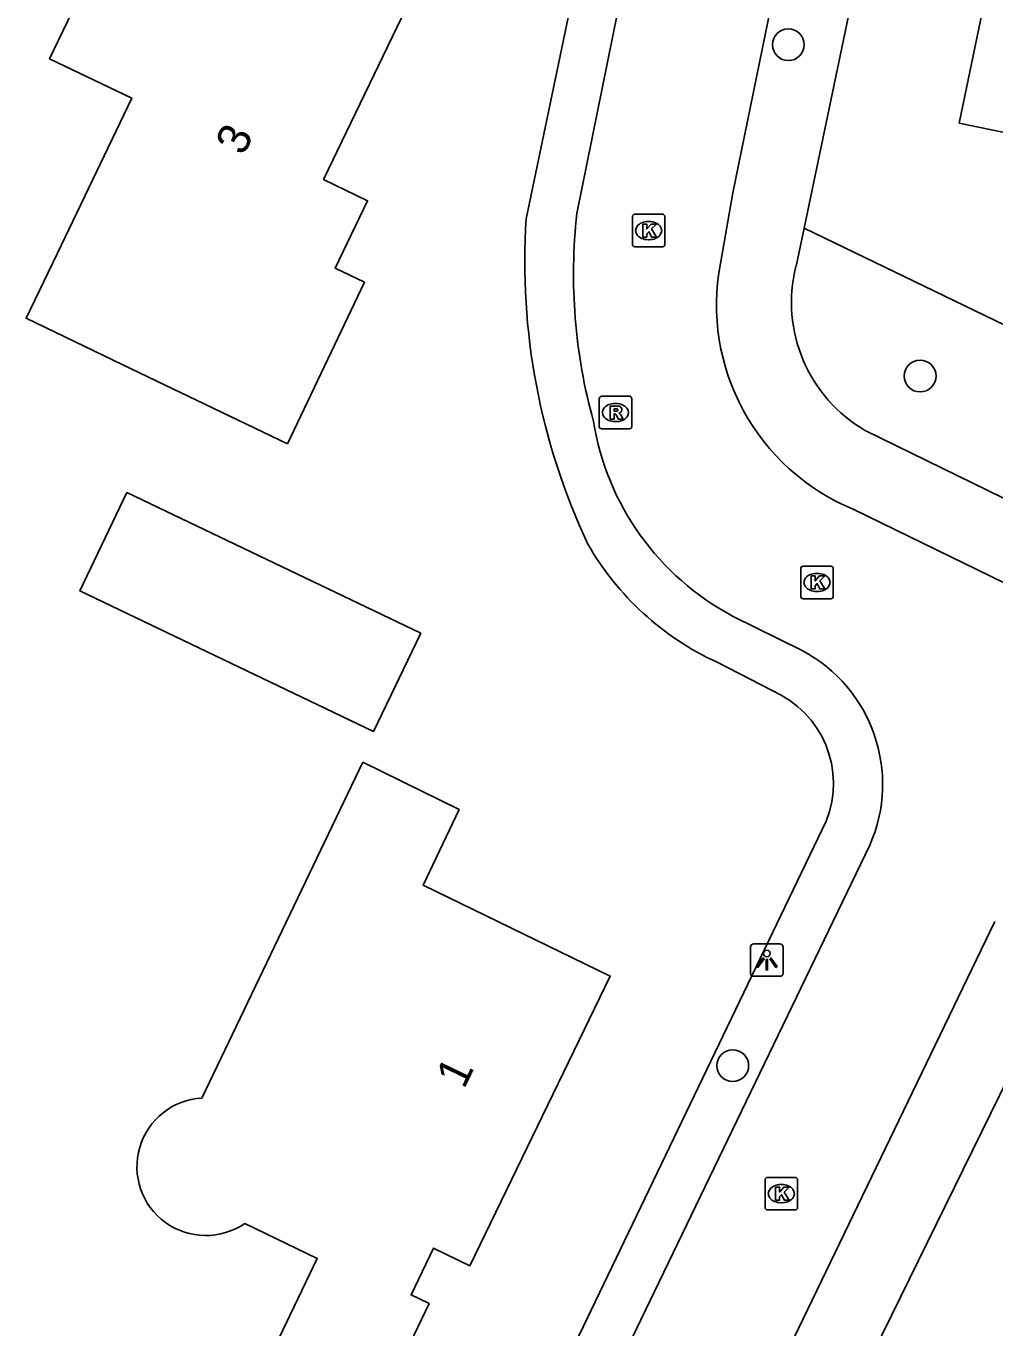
# Model space of a CAD drawing. Extents: x 163427 to 164190, y 380331 to 381641.
# Drawn here: x 163730.97 to 163760.74, y 381512.59 to 381552.62 of the extents above; entities that cross this region are included whole.
import ezdxf

# ---------------------------------------------------------------- set-up
doc = ezdxf.new("R2010")
doc.units = 0
for name, color, linetype in [('IMGEO_Boom', 7, 'Continuous'), ('IMGEO_Groenvoorziening', 7, 'Continuous'), ('IMGEO_Kolk', 7, 'Continuous'), ('IMGEO_Lichtpunt', 7, 'Continuous'), ('IMGEO_Pand', 7, 'Continuous'), ('IMGEO_Pand_nummerreeks', 7, 'Continuous'), ('IMGEO_Rijbaan_lokaal_open', 7, 'Continuous'), ('IMGEO_Rioolput', 7, 'Continuous'), ('IMGEO_Voetpad_open', 7, 'Continuous')]:
    doc.layers.add(name, color=color, linetype=linetype)

msp = doc.modelspace()

# ---------------------------------------------------------------- linework, layer by layer
at = {"layer": 'IMGEO_Boom'}
for centre in [(163754.394, 381552.048), (163758.444, 381541.858), (163752.686, 381520.652)]:
    msp.add_circle(centre, 0.489, dxfattribs=at)
at = {"layer": 'IMGEO_Groenvoorziening'}
msp.add_lwpolyline([(163754.876, 381546.411), (163794.675, 381527.159)], dxfattribs=at)
at = {"layer": 'IMGEO_Kolk'}
for p, q in [((163749.601, 381545.906), (163749.601, 381546.758)), ((163749.676, 381546.832), (163750.528, 381546.832)), ((163750.089, 381546.612), (163750.114, 381546.612)), ((163750.602, 381546.758), (163750.602, 381545.906)), ((163750.528, 381545.832), (163749.676, 381545.832)), ((163750.112, 381546.052), (163750.087, 381546.052)), ((163754.774, 381535.085), (163754.774, 381535.937)), ((163754.849, 381536.011), (163755.701, 381536.011)), ((163755.262, 381535.791), (163755.287, 381535.791)), ((163755.775, 381535.937), (163755.775, 381535.085)), ((163755.701, 381535.011), (163754.849, 381535.011)), ((163755.285, 381535.231), (163755.26, 381535.231)), ((163753.679, 381516.291), (163753.679, 381517.143)), ((163753.754, 381517.217), (163754.606, 381517.217)), ((163754.167, 381516.997), (163754.192, 381516.997)), ((163754.68, 381517.143), (163754.68, 381516.291)), ((163754.19, 381516.437), (163754.165, 381516.437)), ((163754.606, 381516.217), (163753.754, 381516.217))]:
    msp.add_line(p, q, dxfattribs=at)
for points in [[(163749.601, 381545.906), (163749.601, 381546.758)], [(163749.676, 381546.832), (163750.528, 381546.832)], [(163749.922, 381546.532), (163750.045, 381546.532), (163750.045, 381546.381), (163750.175, 381546.532), (163750.339, 381546.532), (163750.193, 381546.381), (163750.346, 381546.132), (163750.194, 381546.132), (163750.109, 381546.296), (163750.045, 381546.229), (163750.045, 381546.132), (163749.922, 381546.132), (163749.922, 381546.532)], [(163750.602, 381546.758), (163750.602, 381545.906)], [(163750.528, 381545.832), (163749.676, 381545.832)], [(163754.774, 381535.085), (163754.774, 381535.937)], [(163754.849, 381536.011), (163755.701, 381536.011)], [(163755.095, 381535.711), (163755.218, 381535.711), (163755.218, 381535.56), (163755.348, 381535.711), (163755.512, 381535.711), (163755.366, 381535.56), (163755.519, 381535.311), (163755.367, 381535.311), (163755.282, 381535.475), (163755.218, 381535.408), (163755.218, 381535.311), (163755.095, 381535.311), (163755.095, 381535.711)], [(163755.775, 381535.937), (163755.775, 381535.085)], [(163755.701, 381535.011), (163754.849, 381535.011)], [(163753.679, 381516.291), (163753.679, 381517.143)], [(163753.754, 381517.217), (163754.606, 381517.217)], [(163754, 381516.917), (163754.123, 381516.917), (163754.123, 381516.766), (163754.253, 381516.917), (163754.417, 381516.917), (163754.271, 381516.766), (163754.424, 381516.517), (163754.272, 381516.517), (163754.187, 381516.681), (163754.123, 381516.614), (163754.123, 381516.517), (163754, 381516.517), (163754, 381516.917)], [(163754.68, 381517.143), (163754.68, 381516.291)], [(163754.606, 381516.217), (163753.754, 381516.217)]]:
    msp.add_lwpolyline(points, dxfattribs=at)
for centre, start, end in [((163749.678, 381546.756), 91.552, 178.448), ((163749.678, 381546.756), 91.552, 178.448), ((163750.526, 381546.756), 1.552, 88.448), ((163750.526, 381546.756), 1.552, 88.448), ((163749.678, 381545.908), 181.552, 268.448), ((163749.678, 381545.908), 181.552, 268.448), ((163750.526, 381545.908), 271.552, 358.448), ((163750.526, 381545.908), 271.552, 358.448), ((163754.851, 381535.935), 91.552, 178.448), ((163754.851, 381535.935), 91.552, 178.448), ((163755.699, 381535.935), 1.552, 88.448), ((163755.699, 381535.935), 1.552, 88.448), ((163754.851, 381535.087), 181.552, 268.448), ((163754.851, 381535.087), 181.552, 268.448), ((163755.699, 381535.087), 271.552, 358.448), ((163755.699, 381535.087), 271.552, 358.448), ((163753.756, 381517.141), 91.552, 178.448), ((163753.756, 381517.141), 91.552, 178.448), ((163754.604, 381517.141), 1.552, 88.448), ((163754.604, 381517.141), 1.552, 88.448), ((163753.756, 381516.293), 181.552, 268.448), ((163753.756, 381516.293), 181.552, 268.448), ((163754.604, 381516.293), 271.552, 358.448), ((163754.604, 381516.293), 271.552, 358.448)]:
    msp.add_arc(centre, 0.0765, start, end, dxfattribs=at)
for centre, major_axis, ratio, start_param, end_param in [((163750.088, 381546.332), (-0.387, 0.002), 0.722429, 4.712389, 7.853982), ((163750.113, 381546.332), (-0.39, 0.002), 0.717154, 1.570796, 4.712389), ((163755.261, 381535.511), (-0.387, 0.002), 0.722429, 4.712389, 7.853982), ((163755.286, 381535.511), (-0.39, 0.002), 0.717154, 1.570796, 4.712389), ((163754.166, 381516.717), (-0.387, 0.002), 0.722429, 4.712389, 7.853982), ((163754.191, 381516.717), (-0.39, 0.002), 0.717154, 1.570796, 4.712389)]:
    msp.add_ellipse(centre, major_axis=major_axis, ratio=ratio, start_param=start_param, end_param=end_param, dxfattribs=at)
at = {"layer": 'IMGEO_Lichtpunt'}
for p, q in [((163753.235, 381524.301), (163753.235, 381523.494)), ((163753.235, 381524.301), (163753.235, 381523.494)), ((163754.137, 381524.396), (163753.329, 381524.396)), ((163754.137, 381524.396), (163753.329, 381524.396)), ((163754.231, 381523.494), (163754.231, 381524.301)), ((163754.231, 381523.494), (163754.231, 381524.301)), ((163753.329, 381523.4), (163754.137, 381523.4)), ((163753.329, 381523.4), (163754.137, 381523.4))]:
    msp.add_line(p, q, dxfattribs=at)
for points in [[(163753.609, 381523.965), (163753.648, 381523.937), (163753.46, 381523.675), (163753.422, 381523.702), (163753.609, 381523.965)], [(163753.711, 381523.917), (163753.758, 381523.917), (163753.758, 381523.595), (163753.711, 381523.595), (163753.711, 381523.917)], [(163753.821, 381523.937), (163753.859, 381523.964), (163754.046, 381523.702), (163754.007, 381523.674), (163753.821, 381523.937)]]:
    msp.add_lwpolyline(points, dxfattribs=at)
msp.add_circle((163753.734, 381524.099), 0.0994, dxfattribs=at)
for centre, start, end in [((163753.329, 381524.301), 90, 180), ((163753.329, 381524.301), 90, 180), ((163754.137, 381524.301), 0, 90), ((163754.137, 381524.301), 0, 90), ((163753.329, 381523.494), 180, 270), ((163753.329, 381523.494), 180, 270), ((163754.137, 381523.494), 270, 0), ((163754.137, 381523.494), 270, 360)]:
    msp.add_arc(centre, 0.0946, start, end, dxfattribs=at)
at = {"layer": 'IMGEO_Pand'}
for points in [[(163766.287, 381565.846), (163764.707, 381566.161), (163764.783, 381566.544), (163763.224, 381566.871), (163759.644, 381549.64), (163765.595, 381548.401), (163766.233, 381551.423), (163765.939, 381551.484), (163767.604, 381559.488), (163776.737, 381555.085), (163780.971, 381553.045), (163784.826, 381561.054), (163780.864, 381562.963), (163782.383, 381566.113)], [(163738.997, 381539.779), (163733.944, 381542.205), (163730.967, 381543.634), (163731.92, 381545.62), (163734.214, 381550.402), (163731.683, 381551.616), (163735.071, 381558.643), (163743.359, 381554.647), (163740.109, 381547.903), (163741.465, 381547.249), (163740.466, 381545.178), (163741.366, 381544.744), (163738.997, 381539.779)], [(163743.096, 381533.952), (163741.65, 381530.931), (163732.621, 381535.253), (163734.068, 381538.275), (163743.096, 381533.952)], [(163736.374, 381519.656), (163741.317, 381529.981)], [(163741.317, 381529.981), (163744.277, 381528.531), (163743.168, 381526.207), (163748.923, 381523.407), (163744.607, 381514.499), (163743.485, 381515.035), (163742.799, 381513.601), (163743.351, 381513.338), (163740.293, 381506.942), (163736.956, 381508.539), (163739.914, 381514.726), (163737.69, 381515.8)]]:
    msp.add_lwpolyline(points, dxfattribs=at)
msp.add_arc((163736.491, 381517.543), 2.116, 93.1792, 304.5089, dxfattribs=at)
at = {"layer": 'IMGEO_Rijbaan_lokaal_open'}
for points in [[(163747.898, 381546.862), (163749.155, 381553.084), (163752.383, 381568.6)], [(163752.306, 381545.321), (163752.684, 381547.494), (163756.834, 381567.791)], [(163786.612, 381523.022), (163772.847, 381529.727), (163756.411, 381537.754)], [(163754.82, 381533.417), (163752.682, 381534.479)], [(163742.315, 381497.297), (163743.1, 381498.851), (163743.604, 381499.848), (163743.677, 381500), (163756.899, 381527.435)], [(163760.744, 381525.086), (163749.235, 381501.225), (163748.64, 381500), (163746.201, 381494.982)]]:
    msp.add_lwpolyline(points, dxfattribs=at)
for centre, radius, start, end in [((163764.657, 381544.975), 16.865, 173.5753, 195.507), ((163758.989, 381544.049), 6.803, 169.2252, 247.7333), ((163756.547, 381541.76), 8.243, 189.0308, 242.0391), ((163752.635, 381529.305), 4.656, 336.3184, 62.0106)]:
    msp.add_arc(centre, radius, start, end, dxfattribs=at)
at = {"layer": 'IMGEO_Rioolput'}
for p, q in [((163748.583, 381540.31), (163748.583, 381541.162)), ((163748.658, 381541.236), (163749.51, 381541.236)), ((163749.071, 381541.016), (163749.096, 381541.016)), ((163749.584, 381541.162), (163749.584, 381540.31)), ((163749.094, 381540.456), (163749.069, 381540.456)), ((163749.51, 381540.236), (163748.658, 381540.236))]:
    msp.add_line(p, q, dxfattribs=at)
for points in [[(163748.583, 381540.31), (163748.583, 381541.162)], [(163748.658, 381541.236), (163749.51, 381541.236)], [(163749.172, 381540.934), (163748.92, 381540.936), (163748.92, 381540.536)], [(163749.098, 381540.855), (163749.044, 381540.855), (163749.044, 381540.774)], [(163749.584, 381541.162), (163749.584, 381540.31)], [(163748.92, 381540.536), (163749.044, 381540.536), (163749.044, 381540.698), (163749.055, 381540.698)], [(163749.044, 381540.774), (163749.096, 381540.774)], [(163749.102, 381540.669), (163749.173, 381540.536), (163749.313, 381540.536), (163749.248, 381540.662)], [(163749.51, 381540.236), (163748.658, 381540.236)]]:
    msp.add_lwpolyline(points, dxfattribs=at)
for centre, radius, start, end in [((163748.66, 381541.16), 0.0765, 91.552, 178.448), ((163748.66, 381541.16), 0.0765, 91.552, 178.448), ((163749.104, 381540.759), 0.0964, 77.0061, 93.1865), ((163749.118, 381540.816), 0.0378, 276.6634, 79.6772), ((163749.171, 381540.824), 0.109, 350.3612, 89.416), ((163749.508, 381541.16), 0.0765, 1.552, 88.448), ((163749.508, 381541.16), 0.0765, 1.552, 88.448), ((163749.054, 381540.645), 0.0533, 26.0293, 88.6989), ((163749.08, 381540.963), 0.19, 274.7715, 282.9687), ((163749.169, 381540.824), 0.112, 277.5842, 350.9817), ((163749.153, 381540.609), 0.108, 29.5134, 73.7905), ((163748.66, 381540.312), 0.0765, 181.552, 268.448), ((163748.66, 381540.312), 0.0765, 181.552, 268.448), ((163749.508, 381540.312), 0.0765, 271.552, 358.448), ((163749.508, 381540.312), 0.0765, 271.552, 358.448)]:
    msp.add_arc(centre, radius, start, end, dxfattribs=at)
for centre, major_axis, ratio, start_param, end_param in [((163749.07, 381540.736), (-0.387, 0.002), 0.722429, 4.712389, 7.853982), ((163749.095, 381540.736), (-0.39, 0.002), 0.717154, 1.570796, 4.712389)]:
    msp.add_ellipse(centre, major_axis=major_axis, ratio=ratio, start_param=start_param, end_param=end_param, dxfattribs=at)
at = {"layer": 'IMGEO_Voetpad_open'}
for points in [[(163750.947, 381568.969), (163747.877, 381554.072), (163746.337, 381546.697)], [(163759.236, 381567.28), (163754.876, 381546.411)], [(163754.63, 381545.233), (163754.876, 381546.411)], [(163788.905, 381524.484), (163774.079, 381531.708), (163756.771, 381540.178)], [(163752.204, 381533.058), (163753.897, 381532.184)], [(163755.555, 381528.169), (163742.257, 381500.486), (163742.008, 381500)], [(163748.094, 381493.596), (163751.203, 381500), (163751.446, 381500.501), (163763.393, 381524.85)]]:
    msp.add_lwpolyline(points, dxfattribs=at)
for centre, radius, start, end in [((163766.694, 381545.374), 20.4, 176.2805, 205.1897), ((163759.04, 381544.12), 4.549, 165.8383, 240.071), ((163755.865, 381541.044), 8.785, 209.7025, 245.3734), ((163752.671, 381529.328), 3.108, 338.1043, 66.7722)]:
    msp.add_arc(centre, radius, start, end, dxfattribs=at)

# ---------------------------------------------------------------- texts
at = {"layer": 'IMGEO_Pand_nummerreeks'}
for s, rotation, p in [('3', 64.2687, (163737.65, 381548.605)), ('1', 64.1494, (163744.427, 381519.906))]:
    msp.add_text(s, height=1, rotation=rotation, dxfattribs=at).set_placement(p)

doc.saveas('drawing.dxf')
